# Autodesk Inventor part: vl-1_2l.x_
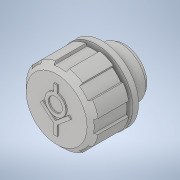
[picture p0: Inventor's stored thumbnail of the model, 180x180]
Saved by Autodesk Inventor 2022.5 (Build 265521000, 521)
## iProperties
Created: 2021-05
Part Number: vl-1_2l.x_
Material: 一般
Document SubType Name: Modeling
Designer: ImaoCorp
Density: 1 g/cm^3
Appearance: 既定
Sending System: SOLIDWORKS 2019-2019304
MC: AMD64
MC_MODEL: Intel64 Family 6 Model 60 Stepping 3, GenuineIntel
OS: Windows_NT
FRU: Parasolid Version 31.0, build 290,  9- 1-2019
FORMAT: text
GUISE: transmit
KEY: vl-1_2l
FILE: vl-1_2l.x_t
DATE: Wed May 19 16:42:53 2021
Author: ImaoCorp
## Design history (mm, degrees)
feature "Base1"
node "ソリッド1"
